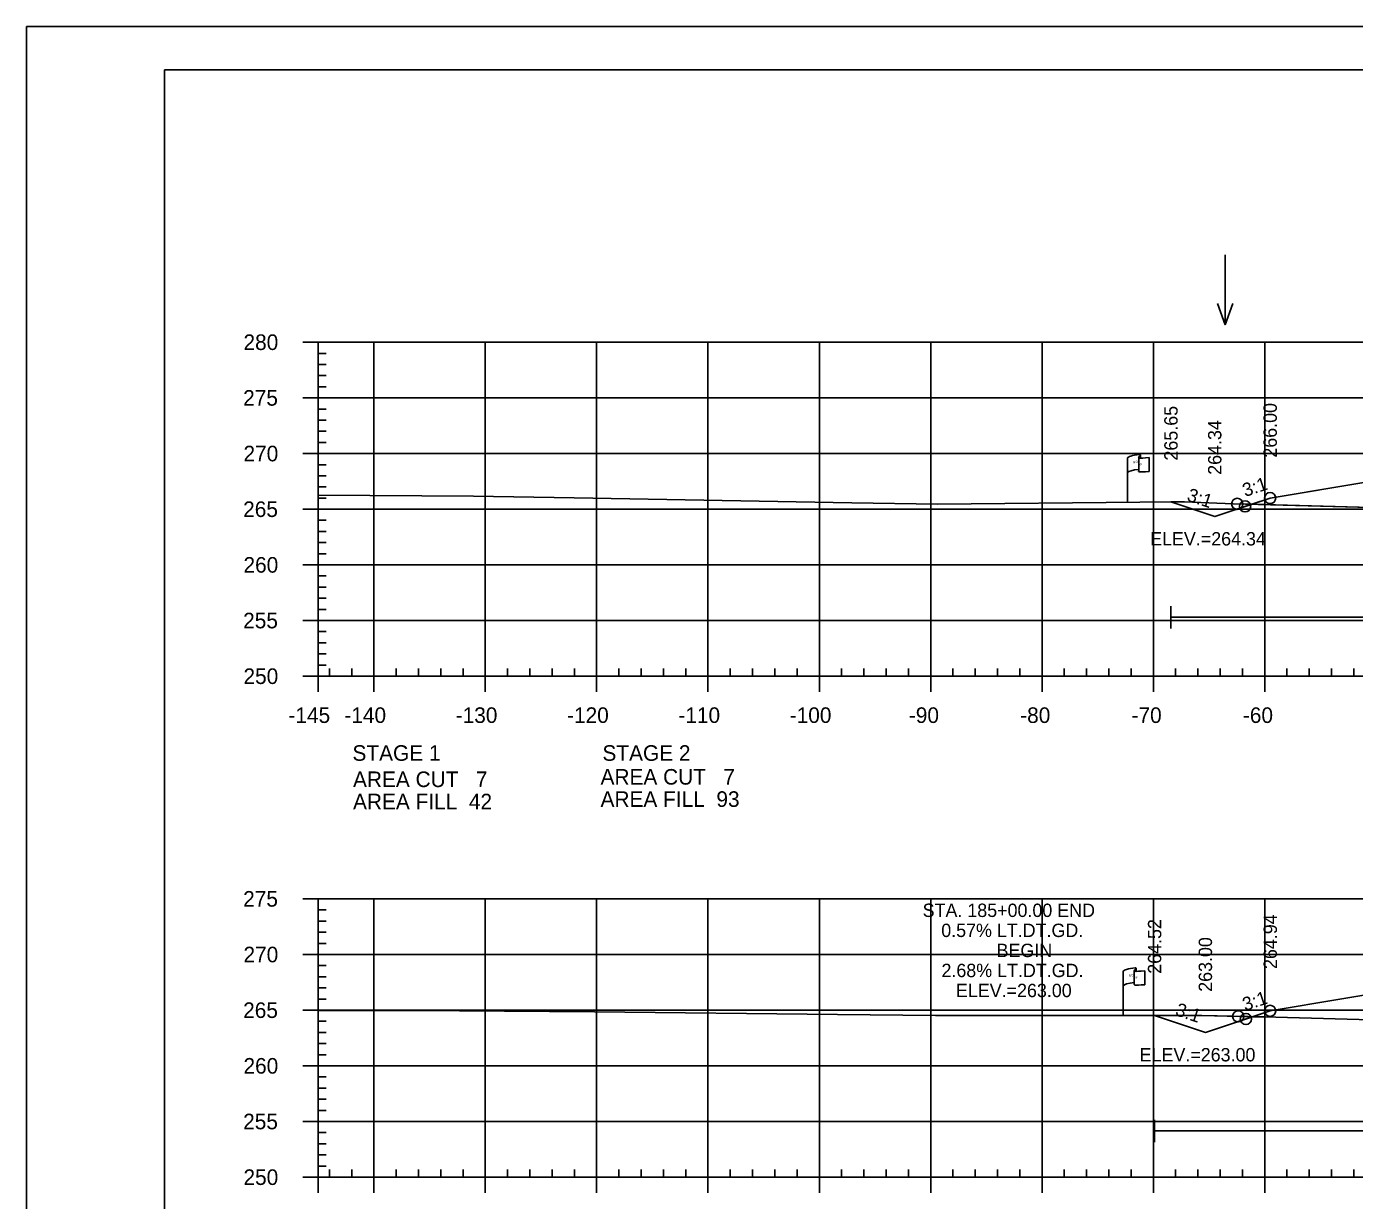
# Model space of a CAD drawing. Extents: x 1365647 to 1367999, y 387113 to 400173.
# Drawn here: x 1365723.7 to 1365842.9, y 388334 to 388439.4 of the extents above; entities that cross this region are included whole.
import ezdxf

# ---------------------------------------------------------------- set-up
doc = ezdxf.new("R2010")
doc.units = 0
for name, color, linetype in [('E_Existing ROW', 7, 'Continuous'), ('R_Axis', 7, 'Continuous'), ('R_Axis Annot', 7, 'Continuous'), ('R_Border', 7, 'Continuous'), ('R_Border Notes', 7, 'Continuous'), ('R_Contours', 7, 'Continuous'), ('R_Exist Surface', 7, 'Continuous'), ('R_Fin Surface', 7, 'Continuous'), ('R_Fin Surface Annot', 7, 'Continuous'), ('R_Grid', 7, 'Continuous'), ('R_No Plot', 7, 'Continuous'), ('R_Water', 7, 'Continuous'), ('R_Water Annot', 7, 'Continuous'), ('R_Xsect Elev', 7, 'Continuous')]:
    doc.layers.add(name, color=color, linetype=linetype)

msp = doc.modelspace()

# ---------------------------------------------------------------- linework, layer by layer
at = {"layer": 'E_Existing ROW'}
for p, q in [((1365822.57, 388396.7), (1365822.57, 388400.65)), ((1365823.57, 388400.74), (1365823.57, 388400.73)), ((1365823.57, 388400.73), (1365823.57, 388399.5)), ((1365823.73, 388400.9), (1365823.73, 388400.66)), ((1365824.5, 388400.7), (1365824.5, 388399.46)), ((1365822.18, 388350.59), (1365822.18, 388354.54)), ((1365823.18, 388354.63), (1365823.18, 388354.62)), ((1365823.18, 388354.62), (1365823.18, 388353.39)), ((1365823.35, 388354.79), (1365823.35, 388354.55)), ((1365824.11, 388354.6), (1365824.11, 388353.36))]:
    msp.add_line(p, q, dxfattribs=at)
for centre, radius, start, end in [((1365823.64, 388400.74), 0.078, 88.6458, 274.2828), ((1365823.66, 388400.9), 0.0783, 263.0712, 93.9564), ((1365823.64, 388399.5), 0.0783, 180, 273.9564), ((1365823.26, 388354.64), 0.078, 88.6458, 274.2828), ((1365823.27, 388354.79), 0.0783, 263.0712, 93.9564), ((1365823.26, 388353.39), 0.0783, 180, 273.9564)]:
    msp.add_arc(centre, radius, start, end, dxfattribs=at)
for centre, major_axis, ratio, start_param, end_param in [((1365824.15, 388400.69), (-1.58, -0.04), 0.19887, 5.030368, 6.283185), ((1365824.86, 388400.8), (-1.23, -0.13), 0.052933, 0.159456, 1.268315), ((1365824.15, 388399.37), (-1.58, -0.04), 0.19887, 5.083035, 6.194897), ((1365824.86, 388399.56), (-1.23, -0.13), 0.052933, 0.159456, 1.268315), ((1365823.77, 388354.58), (-1.58, -0.04), 0.19887, 5.030368, 6.283185), ((1365824.47, 388354.7), (-1.23, -0.13), 0.052933, 0.159456, 1.268315), ((1365823.76, 388353.27), (-1.58, -0.04), 0.19887, 5.083035, 6.194897), ((1365824.47, 388353.46), (-1.23, -0.13), 0.052933, 0.159456, 1.268315)]:
    msp.add_ellipse(centre, major_axis=major_axis, ratio=ratio, start_param=start_param, end_param=end_param, dxfattribs=at)
at = {"layer": 'R_Axis'}
for p, q in [((1365748.49, 388411.07), (1365749.89, 388411.07)), ((1365749.89, 388381.07), (1365749.89, 388411.07)), ((1365749.89, 388410.07), (1365750.59, 388410.07)), ((1365749.89, 388409.07), (1365750.59, 388409.07)), ((1365749.89, 388408.07), (1365750.59, 388408.07)), ((1365749.89, 388407.07), (1365750.59, 388407.07)), ((1365748.49, 388406.07), (1365749.89, 388406.07)), ((1365749.89, 388405.07), (1365750.59, 388405.07)), ((1365749.89, 388404.07), (1365750.59, 388404.07)), ((1365749.89, 388403.07), (1365750.59, 388403.07)), ((1365749.89, 388402.07), (1365750.59, 388402.07)), ((1365748.49, 388401.07), (1365749.89, 388401.07)), ((1365749.89, 388400.07), (1365750.59, 388400.07)), ((1365749.89, 388399.07), (1365750.59, 388399.07)), ((1365749.89, 388398.07), (1365750.59, 388398.07)), ((1365749.89, 388397.07), (1365750.59, 388397.07)), ((1365748.49, 388396.07), (1365749.89, 388396.07)), ((1365749.89, 388395.07), (1365750.59, 388395.07)), ((1365749.89, 388394.07), (1365750.59, 388394.07)), ((1365749.89, 388393.07), (1365750.59, 388393.07)), ((1365748.49, 388391.07), (1365749.89, 388391.07)), ((1365749.89, 388392.07), (1365750.59, 388392.07)), ((1365749.89, 388390.07), (1365750.59, 388390.07)), ((1365749.89, 388389.07), (1365750.59, 388389.07)), ((1365749.89, 388388.07), (1365750.59, 388388.07)), ((1365749.89, 388387.07), (1365750.59, 388387.07)), ((1365748.49, 388386.07), (1365749.89, 388386.07)), ((1365749.89, 388385.07), (1365750.59, 388385.07)), ((1365749.89, 388384.07), (1365750.59, 388384.07)), ((1365749.89, 388383.07), (1365750.59, 388383.07)), ((1365749.89, 388382.07), (1365750.59, 388382.07)), ((1365749.89, 388381.07), (1365749.89, 388381.77)), ((1365750.89, 388381.07), (1365750.89, 388381.77)), ((1365752.89, 388381.07), (1365752.89, 388381.77)), ((1365756.89, 388381.07), (1365756.89, 388381.77)), ((1365758.89, 388381.07), (1365758.89, 388381.77)), ((1365760.89, 388381.07), (1365760.89, 388381.77)), ((1365762.89, 388381.07), (1365762.89, 388381.77)), ((1365766.89, 388381.07), (1365766.89, 388381.77)), ((1365768.89, 388381.07), (1365768.89, 388381.77)), ((1365770.89, 388381.07), (1365770.89, 388381.77)), ((1365772.89, 388381.07), (1365772.89, 388381.77)), ((1365776.89, 388381.07), (1365776.89, 388381.77)), ((1365778.89, 388381.07), (1365778.89, 388381.77)), ((1365780.89, 388381.07), (1365780.89, 388381.77)), ((1365782.89, 388381.07), (1365782.89, 388381.77)), ((1365786.89, 388381.07), (1365786.89, 388381.77)), ((1365788.89, 388381.07), (1365788.89, 388381.77)), ((1365790.89, 388381.07), (1365790.89, 388381.77)), ((1365792.89, 388381.07), (1365792.89, 388381.77)), ((1365796.89, 388381.07), (1365796.89, 388381.77)), ((1365798.89, 388381.07), (1365798.89, 388381.77)), ((1365800.89, 388381.07), (1365800.89, 388381.77)), ((1365802.89, 388381.07), (1365802.89, 388381.77)), ((1365806.89, 388381.07), (1365806.89, 388381.77)), ((1365808.89, 388381.07), (1365808.89, 388381.77)), ((1365810.89, 388381.07), (1365810.89, 388381.77)), ((1365812.89, 388381.07), (1365812.89, 388381.77)), ((1365816.89, 388381.07), (1365816.89, 388381.77)), ((1365818.89, 388381.07), (1365818.89, 388381.77)), ((1365820.89, 388381.07), (1365820.89, 388381.77)), ((1365822.89, 388381.07), (1365822.89, 388381.77)), ((1365826.89, 388381.07), (1365826.89, 388381.77)), ((1365828.89, 388381.07), (1365828.89, 388381.77)), ((1365830.89, 388381.07), (1365830.89, 388381.77)), ((1365832.89, 388381.07), (1365832.89, 388381.77)), ((1365836.89, 388381.07), (1365836.89, 388381.77)), ((1365838.89, 388381.07), (1365838.89, 388381.77)), ((1365840.89, 388381.07), (1365840.89, 388381.77)), ((1365842.89, 388381.07), (1365842.89, 388381.77)), ((1365748.49, 388381.07), (1365749.89, 388381.07)), ((1365749.89, 388381.07), (1366039.89, 388381.07)), ((1365749.89, 388379.67), (1365749.89, 388381.07)), ((1365754.89, 388379.67), (1365754.89, 388381.07)), ((1365764.89, 388379.67), (1365764.89, 388381.07)), ((1365774.89, 388379.67), (1365774.89, 388381.07)), ((1365784.89, 388379.67), (1365784.89, 388381.07)), ((1365794.89, 388379.67), (1365794.89, 388381.07)), ((1365804.89, 388379.67), (1365804.89, 388381.07)), ((1365814.89, 388379.67), (1365814.89, 388381.07)), ((1365824.89, 388379.67), (1365824.89, 388381.07)), ((1365834.89, 388379.67), (1365834.89, 388381.07)), ((1365748.49, 388361.07), (1365749.89, 388361.07)), ((1365749.89, 388336.07), (1365749.89, 388361.07)), ((1365749.89, 388360.07), (1365750.59, 388360.07)), ((1365749.89, 388359.07), (1365750.59, 388359.07)), ((1365749.89, 388358.07), (1365750.59, 388358.07)), ((1365749.89, 388357.07), (1365750.59, 388357.07)), ((1365748.49, 388356.07), (1365749.89, 388356.07)), ((1365749.89, 388355.07), (1365750.59, 388355.07)), ((1365749.89, 388354.07), (1365750.59, 388354.07)), ((1365749.89, 388353.07), (1365750.59, 388353.07)), ((1365749.89, 388352.07), (1365750.59, 388352.07)), ((1365748.49, 388351.07), (1365749.89, 388351.07)), ((1365749.89, 388350.07), (1365750.59, 388350.07)), ((1365749.89, 388349.07), (1365750.59, 388349.07)), ((1365749.89, 388348.07), (1365750.59, 388348.07)), ((1365749.89, 388347.07), (1365750.59, 388347.07)), ((1365748.49, 388346.07), (1365749.89, 388346.07)), ((1365749.89, 388345.07), (1365750.59, 388345.07)), ((1365749.89, 388344.07), (1365750.59, 388344.07)), ((1365749.89, 388343.07), (1365750.59, 388343.07)), ((1365748.49, 388341.07), (1365749.89, 388341.07)), ((1365749.89, 388342.07), (1365750.59, 388342.07)), ((1365749.89, 388340.07), (1365750.59, 388340.07)), ((1365749.89, 388339.07), (1365750.59, 388339.07)), ((1365749.89, 388338.07), (1365750.59, 388338.07)), ((1365749.89, 388337.07), (1365750.59, 388337.07)), ((1365749.89, 388336.07), (1365749.89, 388336.77)), ((1365750.89, 388336.07), (1365750.89, 388336.77)), ((1365752.89, 388336.07), (1365752.89, 388336.77)), ((1365756.89, 388336.07), (1365756.89, 388336.77)), ((1365758.89, 388336.07), (1365758.89, 388336.77)), ((1365760.89, 388336.07), (1365760.89, 388336.77)), ((1365762.89, 388336.07), (1365762.89, 388336.77)), ((1365766.89, 388336.07), (1365766.89, 388336.77)), ((1365768.89, 388336.07), (1365768.89, 388336.77)), ((1365770.89, 388336.07), (1365770.89, 388336.77)), ((1365772.89, 388336.07), (1365772.89, 388336.77)), ((1365776.89, 388336.07), (1365776.89, 388336.77)), ((1365778.89, 388336.07), (1365778.89, 388336.77)), ((1365780.89, 388336.07), (1365780.89, 388336.77)), ((1365782.89, 388336.07), (1365782.89, 388336.77)), ((1365786.89, 388336.07), (1365786.89, 388336.77)), ((1365788.89, 388336.07), (1365788.89, 388336.77)), ((1365790.89, 388336.07), (1365790.89, 388336.77)), ((1365792.89, 388336.07), (1365792.89, 388336.77)), ((1365796.89, 388336.07), (1365796.89, 388336.77)), ((1365798.89, 388336.07), (1365798.89, 388336.77)), ((1365800.89, 388336.07), (1365800.89, 388336.77)), ((1365802.89, 388336.07), (1365802.89, 388336.77)), ((1365806.89, 388336.07), (1365806.89, 388336.77)), ((1365808.89, 388336.07), (1365808.89, 388336.77)), ((1365810.89, 388336.07), (1365810.89, 388336.77)), ((1365812.89, 388336.07), (1365812.89, 388336.77)), ((1365816.89, 388336.07), (1365816.89, 388336.77)), ((1365818.89, 388336.07), (1365818.89, 388336.77)), ((1365820.89, 388336.07), (1365820.89, 388336.77)), ((1365822.89, 388336.07), (1365822.89, 388336.77)), ((1365826.89, 388336.07), (1365826.89, 388336.77)), ((1365828.89, 388336.07), (1365828.89, 388336.77)), ((1365830.89, 388336.07), (1365830.89, 388336.77)), ((1365832.89, 388336.07), (1365832.89, 388336.77)), ((1365836.89, 388336.07), (1365836.89, 388336.77)), ((1365838.89, 388336.07), (1365838.89, 388336.77)), ((1365840.89, 388336.07), (1365840.89, 388336.77)), ((1365842.89, 388336.07), (1365842.89, 388336.77)), ((1365748.49, 388336.07), (1365749.89, 388336.07)), ((1365749.89, 388336.07), (1366039.89, 388336.07)), ((1365749.89, 388334.67), (1365749.89, 388336.07)), ((1365754.89, 388334.67), (1365754.89, 388336.07)), ((1365764.89, 388334.67), (1365764.89, 388336.07)), ((1365774.89, 388334.67), (1365774.89, 388336.07)), ((1365784.89, 388334.67), (1365784.89, 388336.07)), ((1365794.89, 388334.67), (1365794.89, 388336.07)), ((1365804.89, 388334.67), (1365804.89, 388336.07)), ((1365814.89, 388334.67), (1365814.89, 388336.07)), ((1365824.89, 388334.67), (1365824.89, 388336.07)), ((1365834.89, 388334.67), (1365834.89, 388336.07))]:
    msp.add_line(p, q, dxfattribs=at)
at = {"layer": 'R_Border'}
for p, q in [((1365736.09, 388435.53), (1366052.27, 388435.53)), ((1365736.09, 388230.07), (1365736.09, 388435.53))]:
    msp.add_line(p, q, dxfattribs=at)
at = {"layer": 'R_Contours'}
for points in [[(1365833.73, 388396.52), (1365845.49, 388396.18), (1365850.25, 388396.22), (1365852.84, 388396.23), (1365857.14, 388396.24), (1365858.93, 388396.26), (1365862.65, 388396.69), (1365869.44, 388397.47), (1365873.34, 388398.67), (1365876.77, 388399.78), (1365863.38, 388399.52), (1365848.26, 388399.21), (1365835.38, 388397.07)], [(1365826.47, 388396.72), (1365827.69, 388396.72), (1365832.05, 388396.56), (1365833.73, 388396.52), (1365830.4, 388395.41)], [(1365833.8, 388350.48), (1365834.81, 388350.46), (1365846.59, 388350.14), (1365848.91, 388350.21), (1365852.52, 388350.27), (1365856, 388350.3), (1365859.91, 388350.3), (1365867.85, 388351.39), (1365869.65, 388351.63), (1365873.6, 388352.78), (1365876.71, 388353.73), (1365863.38, 388353.46), (1365848.26, 388353.16), (1365835.38, 388351.01)], [(1365825, 388350.59), (1365829.23, 388350.58), (1365833.8, 388350.48), (1365829.56, 388349.07)]]:
    msp.add_lwpolyline(points, close=True, dxfattribs=at)
at = {"layer": 'R_Exist Surface'}
for points in [[(1365749.89, 388397.33), (1365763.84, 388397.24), (1365772.86, 388397.09), (1365797.81, 388396.64), (1365805.49, 388396.52), (1365823.67, 388396.71), (1365827.69, 388396.72), (1365832.05, 388396.56), (1365845.49, 388396.18)], [(1365749.89, 388351.04), (1365762.56, 388351.01), (1365774.71, 388350.92), (1365796.51, 388350.69), (1365805.32, 388350.6), (1365810.87, 388350.6), (1365829.23, 388350.58), (1365834.81, 388350.46), (1365846.59, 388350.14)]]:
    msp.add_lwpolyline(points, dxfattribs=at)
at = {"layer": 'R_Fin Surface'}
for points in [[(1365826.47, 388396.72), (1365830.4, 388395.41), (1365835.38, 388397.07), (1365848.26, 388399.21), (1365857.38, 388400.74), (1365863.38, 388400.98), (1365865.38, 388401.02), (1365894.88, 388401.61), (1365924.38, 388401.02), (1365926.38, 388400.98), (1365932.38, 388400.74), (1365941.51, 388399.21), (1365954.38, 388397.07), (1365961.08, 388394.84), (1365964.47, 388395.96)], [(1365835.38, 388397.07), (1365853.09, 388400.02), (1365857.38, 388400.74), (1365863.38, 388400.98), (1365865.38, 388401.02), (1365894.88, 388401.61), (1365924.38, 388401.02), (1365926.38, 388400.98), (1365932.38, 388400.74), (1365936.68, 388400.02), (1365954.38, 388397.07), (1365956.15, 388396.48)], [(1365825, 388350.59), (1365829.56, 388349.07), (1365835.38, 388351.01), (1365848.26, 388353.16), (1365857.38, 388354.68), (1365863.38, 388354.92), (1365865.38, 388354.96), (1365894.88, 388355.55), (1365924.38, 388354.96), (1365926.38, 388354.92), (1365932.38, 388354.68), (1365941.51, 388353.16), (1365954.38, 388351.01), (1365960.6, 388348.94), (1365962.39, 388349.54)]]:
    msp.add_lwpolyline(points, dxfattribs=at)
at = {"layer": 'R_Grid'}
for p, q in [((1365749.89, 388411.07), (1366039.89, 388411.07)), ((1365749.89, 388381.07), (1365749.89, 388411.07)), ((1365754.89, 388381.07), (1365754.89, 388411.07)), ((1365764.89, 388381.07), (1365764.89, 388411.07)), ((1365774.89, 388381.07), (1365774.89, 388411.07)), ((1365784.89, 388381.07), (1365784.89, 388411.07)), ((1365794.89, 388381.07), (1365794.89, 388411.07)), ((1365804.89, 388381.07), (1365804.89, 388411.07)), ((1365814.89, 388381.07), (1365814.89, 388411.07)), ((1365824.89, 388381.07), (1365824.89, 388411.07)), ((1365834.89, 388381.07), (1365834.89, 388411.07)), ((1365749.89, 388406.07), (1366039.89, 388406.07)), ((1365749.89, 388401.07), (1366039.89, 388401.07)), ((1365749.89, 388396.07), (1366039.89, 388396.07)), ((1365749.89, 388391.07), (1366039.89, 388391.07)), ((1365749.89, 388386.07), (1366039.89, 388386.07)), ((1365749.89, 388381.07), (1366039.89, 388381.07)), ((1365749.89, 388361.07), (1366039.89, 388361.07)), ((1365749.89, 388336.07), (1365749.89, 388361.07)), ((1365754.89, 388336.07), (1365754.89, 388361.07)), ((1365764.89, 388336.07), (1365764.89, 388361.07)), ((1365774.89, 388336.07), (1365774.89, 388361.07)), ((1365784.89, 388336.07), (1365784.89, 388361.07)), ((1365794.89, 388336.07), (1365794.89, 388361.07)), ((1365804.89, 388336.07), (1365804.89, 388361.07)), ((1365814.89, 388336.07), (1365814.89, 388361.07)), ((1365824.89, 388336.07), (1365824.89, 388361.07)), ((1365834.89, 388336.07), (1365834.89, 388361.07)), ((1365749.89, 388356.07), (1366039.89, 388356.07)), ((1365749.89, 388351.07), (1366039.89, 388351.07)), ((1365749.89, 388346.07), (1366039.89, 388346.07)), ((1365749.89, 388341.07), (1366039.89, 388341.07)), ((1365749.89, 388336.07), (1366039.89, 388336.07))]:
    msp.add_line(p, q, dxfattribs=at)
at = {"layer": 'R_No Plot'}
msp.add_line((1365723.69, 388439.42), (1366057.03, 388439.42), dxfattribs=at)
msp.add_lwpolyline([(1365723.69, 388439.42), (1366057.03, 388439.42), (1366057.03, 388226.09), (1365723.69, 388226.09)], close=True, dxfattribs=at)
for centre in [(1365832.42, 388396.55), (1365832.42, 388396.55), (1365835.38, 388397.07), (1365835.38, 388397.07), (1365835.38, 388397.07), (1365835.38, 388397.07), (1365835.38, 388397.07), (1365833.13, 388396.32), (1365833.13, 388396.32), (1365832.51, 388350.51), (1365832.51, 388350.51), (1365833.2, 388350.28), (1365833.2, 388350.28), (1365835.38, 388351.01), (1365835.38, 388351.01), (1365835.38, 388351.01), (1365835.38, 388351.01), (1365835.38, 388351.01)]:
    msp.add_circle(centre, 0.5, dxfattribs=at)
at = {"layer": 'R_Water'}
for p, q in [((1365826.47, 388385.36), (1365826.47, 388387.36)), ((1365826.47, 388386.36), (1365882.9, 388386.36)), ((1365825, 388339.22), (1365825, 388341.22)), ((1365825, 388340.22), (1365883.07, 388340.22))]:
    msp.add_line(p, q, dxfattribs=at)
at = {"layer": 'R_Water Annot'}
for p, q in [((1365831.34, 388418.92), (1365831.34, 388412.63)), ((1365831.34, 388412.63), (1365830.64, 388414.56)), ((1365831.34, 388412.63), (1365832.04, 388414.56))]:
    msp.add_line(p, q, dxfattribs=at)

# ---------------------------------------------------------------- texts
at = {"layer": 'E_Existing ROW'}
for s, height, rotation, p in [('DWB 11-9-07', 0.001, 90, (1365823.73, 388400.66)), ('R ', 0.2, 9.9884, (1365823.09, 388400.15)), (' O', 0.2, 9.9884, (1365823.24, 388400.19)), ('W', 0.2, 351.1788, (1365823.57, 388400.02)), ('DWB 11-9-07', 0.001, 5.0717, (1365824.49, 388399.46)), ('DWB 11-9-07', 0.001, 90, (1365822.57, 388396.7)), ('R ', 0.2, 9.9884, (1365822.7, 388354.04)), (' O', 0.2, 9.9884, (1365822.85, 388354.09)), ('W', 0.2, 351.1788, (1365823.18, 388353.92)), ('DWB 11-9-07', 0.001, 90, (1365823.35, 388354.55)), ('DWB 11-9-07', 0.001, 5.0717, (1365824.1, 388353.36)), ('DWB 11-9-07', 0.001, 90, (1365822.18, 388350.59))]:
    msp.add_text(s, height=height, rotation=rotation, dxfattribs=at).set_placement(p)
at = {"layer": 'R_Axis Annot'}
for s, p in [('280', (1365743.17, 388410.37)), ('275', (1365743.14, 388405.37)), ('270', (1365743.17, 388400.37)), ('265', (1365743.14, 388395.37)), ('260', (1365743.17, 388390.37)), ('255', (1365743.14, 388385.37)), ('250', (1365743.17, 388380.37)), ('-145', (1365747.21, 388376.87)), ('-140', (1365752.23, 388376.87)), ('-130', (1365762.23, 388376.87)), ('-120', (1365772.23, 388376.87)), ('-110', (1365782.23, 388376.87)), ('-100', (1365792.23, 388376.87)), ('-90', (1365802.93, 388376.87)), ('-80', (1365812.93, 388376.87)), ('-70', (1365822.93, 388376.87)), ('-60', (1365832.93, 388376.87)), ('STAGE 1', (1365752.96, 388373.47)), ('STAGE 2', (1365775.41, 388373.47)), ('AREA CUT   7', (1365753.01, 388371.11)), ('AREA CUT   7', (1365775.24, 388371.33)), ('AREA FILL  93', (1365775.24, 388369.33)), ('AREA FILL  42', (1365753.01, 388369.11)), ('275', (1365743.14, 388360.37)), ('270', (1365743.17, 388355.37)), ('265', (1365743.14, 388350.37)), ('260', (1365743.17, 388345.37)), ('255', (1365743.14, 388340.37)), ('250', (1365743.17, 388335.37))]:
    msp.add_text(s, height=1.4, dxfattribs=at).set_placement(p)
at = {"layer": 'R_Border Notes'}
for s, p in [('ELEV.=264.34', (1365824.6, 388392.81)), ('ELEV.=263.00', (1365823.66, 388346.47))]:
    msp.add_text(s, height=1.2, dxfattribs=at).set_placement(p)
at = {"layer": 'R_Fin Surface Annot'}
for rotation, p in [(18.4349, (1365833.13, 388397.16)), (341.5651, (1365827.83, 388396.86)), (341.5651, (1365826.79, 388350.63)), (18.4349, (1365833.13, 388350.98))]:
    msp.add_text('3:1', height=1.2, rotation=rotation, dxfattribs=at).set_placement(p)
at = {"layer": 'R_Water'}
for s, p in [('STA. 185+00.00 END', (1365804.17, 388359.44)), ('0.57% LT.DT.GD.', (1365805.84, 388357.64)), ('BEGIN', (1365810.81, 388355.84)), ('2.68% LT.DT.GD.', (1365805.86, 388354.04)), ('ELEV.=263.00', (1365807.16, 388352.24))]:
    msp.add_text(s, height=1.2, dxfattribs=at).set_placement(p)
at = {"layer": 'R_Xsect Elev'}
for s, p in [('266.00', (1365835.98, 388400.7)), ('265.65', (1365827.07, 388400.44)), ('264.34', (1365831, 388399.16)), ('264.52', (1365825.6, 388354.34)), ('264.94', (1365835.99, 388354.77)), ('263.00', (1365830.16, 388352.72))]:
    msp.add_text(s, height=1.2, rotation=90, dxfattribs=at).set_placement(p)

doc.saveas('drawing.dxf')
